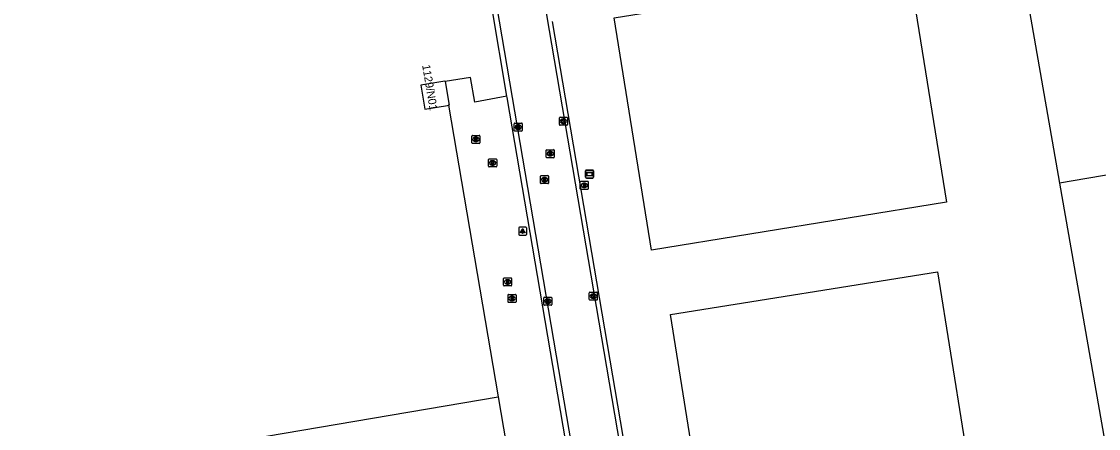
# Model space of a CAD drawing. Extents: x 154324 to 155743, y 382939 to 384183.
# Drawn here: x 154819.6 to 154954.2, y 383617.3 to 383668.1 of the extents above; entities that cross this region are included whole.
import ezdxf

# ---------------------------------------------------------------- set-up
doc = ezdxf.new("R2010")
doc.units = 0
for name, color, linetype in [('IMGEO_Brandkraan', 7, 'Continuous'), ('IMGEO_Erf', 7, 'Continuous'), ('IMGEO_Grasland_agrarisch', 7, 'Continuous'), ('IMGEO_Kolk', 7, 'Continuous'), ('IMGEO_Lichtpunt', 7, 'Continuous'), ('IMGEO_Muur', 7, 'Continuous'), ('IMGEO_Pand', 7, 'Continuous'), ('IMGEO_Pand_nummerreeks', 7, 'Continuous'), ('IMGEO_Pand_vergunning_verleend', 7, 'Continuous'), ('IMGEO_Rijbaan_lokaal_gesloten', 7, 'Continuous'), ('IMGEO_Rijbaan_lokaal_open', 7, 'Continuous'), ('IMGEO_Rioolput', 7, 'Continuous'), ('IMGEO_Verklikker', 7, 'Continuous')]:
    doc.layers.add(name, color=color, linetype=linetype)

msp = doc.modelspace()

# ---------------------------------------------------------------- linework, layer by layer
at = {"layer": 'IMGEO_Brandkraan'}
for p, q in [((154889.46, 383647.21), (154889.46, 383648.06)), ((154889.54, 383648.13), (154890.39, 383648.13)), ((154889.95, 383647.91), (154889.97, 383647.91)), ((154890.46, 383648.06), (154890.46, 383647.21)), ((154890.39, 383647.13), (154889.54, 383647.13)), ((154889.97, 383647.35), (154889.95, 383647.35))]:
    msp.add_line(p, q, dxfattribs=at)
for points in [[(154889.46, 383647.21), (154889.46, 383648.06)], [(154889.54, 383648.13), (154890.39, 383648.13)], [(154889.81, 383647.83), (154889.81, 383647.43), (154890.02, 383647.43)], [(154890.04, 383647.83), (154889.81, 383647.83)], [(154889.99, 383647.75), (154889.93, 383647.75), (154889.93, 383647.68)], [(154889.93, 383647.68), (154889.99, 383647.68)], [(154890, 383647.6), (154889.93, 383647.6), (154889.93, 383647.52)], [(154889.93, 383647.52), (154890, 383647.52)], [(154890.46, 383648.06), (154890.46, 383647.21)], [(154890.39, 383647.13), (154889.54, 383647.13)]]:
    msp.add_lwpolyline(points, dxfattribs=at)
for centre, radius, start, end in [((154889.54, 383648.06), 0.0765, 91.552, 178.448), ((154889.54, 383648.06), 0.0765, 91.552, 178.448), ((154889.99, 383647.71), 0.0379, 267.8285, 90.9355), ((154890, 383647.56), 0.0404, 269.8759, 90.5077), ((154890.03, 383647.68), 0.251, 268.6676, 293.5347), ((154890.04, 383647.69), 0.145, 59.4692, 91.5367), ((154890.07, 383647.74), 0.0922, 285.5137, 58.1501), ((154890.07, 383647.54), 0.105, 301.3115, 78.989), ((154890.39, 383648.06), 0.0765, 1.552, 88.448), ((154890.39, 383648.06), 0.0765, 1.552, 88.448), ((154889.54, 383647.21), 0.0765, 181.552, 268.448), ((154889.54, 383647.21), 0.0765, 181.552, 268.448), ((154890.39, 383647.21), 0.0765, 271.552, 358.448), ((154890.39, 383647.21), 0.0765, 271.552, 358.448)]:
    msp.add_arc(centre, radius, start, end, dxfattribs=at)
for centre, major_axis, ratio, start_param, end_param in [((154889.95, 383647.63), (-0.387, 0.002), 0.722429, 4.712389, 7.853982), ((154889.97, 383647.63), (-0.39, 0.002), 0.717154, 1.570796, 4.712389)]:
    msp.add_ellipse(centre, major_axis=major_axis, ratio=ratio, start_param=start_param, end_param=end_param, dxfattribs=at)
at = {"layer": 'IMGEO_Erf'}
for points in [[(154880.3, 383658.76), (154876.27, 383658.02), (154875.75, 383661.08), (154872.56, 383660.61)], [(154872.98, 383657.63), (154879.18, 383621.22)]]:
    msp.add_lwpolyline(points, dxfattribs=at)
at = {"layer": 'IMGEO_Grasland_agrarisch'}
msp.add_lwpolyline([(154895.23, 383669.68), (154944.1, 383677.97), (154949.34, 383647.91), (154982.71, 383457.88)], dxfattribs=at)
at = {"layer": 'IMGEO_Kolk'}
for p, q in [((154886.85, 383655.21), (154886.85, 383656.06)), ((154886.93, 383656.14), (154887.78, 383656.14)), ((154887.34, 383655.92), (154887.36, 383655.92)), ((154887.85, 383656.06), (154887.85, 383655.21)), ((154881.2, 383654.47), (154881.2, 383655.33)), ((154881.28, 383655.4), (154882.13, 383655.4)), ((154882.13, 383654.4), (154881.28, 383654.4)), ((154881.69, 383655.18), (154881.72, 383655.18)), ((154881.71, 383654.62), (154881.69, 383654.62)), ((154882.2, 383655.33), (154882.2, 383654.47)), ((154887.78, 383655.14), (154886.93, 383655.14)), ((154887.36, 383655.36), (154887.34, 383655.36)), ((154890.59, 383633.37), (154890.59, 383634.22)), ((154890.67, 383634.29), (154891.52, 383634.29)), ((154891.08, 383634.07), (154891.11, 383634.07)), ((154891.59, 383634.22), (154891.59, 383633.37)), ((154884.91, 383632.73), (154884.91, 383633.59)), ((154884.98, 383633.66), (154885.83, 383633.66)), ((154885.83, 383632.66), (154884.98, 383632.66)), ((154885.39, 383633.44), (154885.42, 383633.44)), ((154885.42, 383632.88), (154885.39, 383632.88)), ((154885.91, 383633.59), (154885.91, 383632.73)), ((154891.52, 383633.29), (154890.67, 383633.29)), ((154891.1, 383633.51), (154891.08, 383633.51))]:
    msp.add_line(p, q, dxfattribs=at)
for points in [[(154886.85, 383655.21), (154886.85, 383656.06)], [(154886.93, 383656.14), (154887.78, 383656.14)], [(154887.17, 383655.84), (154887.3, 383655.84), (154887.3, 383655.69), (154887.42, 383655.84), (154887.59, 383655.84), (154887.44, 383655.69), (154887.6, 383655.44), (154887.44, 383655.44), (154887.36, 383655.6), (154887.3, 383655.53), (154887.3, 383655.44), (154887.17, 383655.44), (154887.17, 383655.84)], [(154887.85, 383656.06), (154887.85, 383655.21)], [(154881.2, 383654.47), (154881.2, 383655.33)], [(154881.28, 383655.4), (154882.13, 383655.4)], [(154882.13, 383654.4), (154881.28, 383654.4)], [(154881.52, 383655.1), (154881.65, 383655.1), (154881.65, 383654.95), (154881.78, 383655.1), (154881.94, 383655.1), (154881.79, 383654.95), (154881.95, 383654.7), (154881.79, 383654.7), (154881.71, 383654.86), (154881.65, 383654.8), (154881.65, 383654.7), (154881.52, 383654.7), (154881.52, 383655.1)], [(154882.2, 383655.33), (154882.2, 383654.47)], [(154887.78, 383655.14), (154886.93, 383655.14)], [(154890.59, 383633.37), (154890.59, 383634.22)], [(154890.67, 383634.29), (154891.52, 383634.29)], [(154890.91, 383633.99), (154891.04, 383633.99), (154891.04, 383633.84), (154891.17, 383633.99), (154891.33, 383633.99), (154891.19, 383633.84), (154891.34, 383633.59), (154891.19, 383633.59), (154891.1, 383633.76), (154891.04, 383633.69), (154891.04, 383633.59), (154890.91, 383633.59), (154890.91, 383633.99)], [(154891.59, 383634.22), (154891.59, 383633.37)], [(154884.91, 383632.73), (154884.91, 383633.59)], [(154884.98, 383633.66), (154885.83, 383633.66)], [(154885.83, 383632.66), (154884.98, 383632.66)], [(154885.23, 383633.36), (154885.35, 383633.36), (154885.35, 383633.21), (154885.48, 383633.36), (154885.64, 383633.36), (154885.5, 383633.21), (154885.65, 383632.96), (154885.5, 383632.96), (154885.41, 383633.13), (154885.35, 383633.06), (154885.35, 383632.96), (154885.23, 383632.96), (154885.23, 383633.36)], [(154885.91, 383633.59), (154885.91, 383632.73)], [(154891.52, 383633.29), (154890.67, 383633.29)]]:
    msp.add_lwpolyline(points, dxfattribs=at)
for centre, start, end in [((154886.93, 383656.06), 91.552, 178.448), ((154886.93, 383656.06), 91.552, 178.448), ((154887.78, 383656.06), 1.552, 88.448), ((154887.78, 383656.06), 1.552, 88.448), ((154881.28, 383655.32), 91.552, 178.448), ((154881.28, 383655.32), 91.552, 178.448), ((154881.28, 383654.47), 181.552, 268.448), ((154881.28, 383654.47), 181.552, 268.448), ((154882.13, 383655.32), 1.552, 88.448), ((154882.13, 383655.32), 1.552, 88.448), ((154882.13, 383654.47), 271.552, 358.448), ((154882.13, 383654.47), 271.552, 358.448), ((154886.93, 383655.21), 181.552, 268.448), ((154886.93, 383655.21), 181.552, 268.448), ((154887.78, 383655.21), 271.552, 358.448), ((154887.78, 383655.21), 271.552, 358.448), ((154890.67, 383634.22), 91.552, 178.448), ((154890.67, 383634.22), 91.552, 178.448), ((154891.52, 383634.22), 1.552, 88.448), ((154891.52, 383634.22), 1.552, 88.448), ((154884.98, 383633.59), 91.552, 178.448), ((154884.98, 383633.59), 91.552, 178.448), ((154884.98, 383632.74), 181.552, 268.448), ((154884.98, 383632.74), 181.552, 268.448), ((154885.83, 383633.59), 1.552, 88.448), ((154885.83, 383633.59), 1.552, 88.448), ((154885.83, 383632.74), 271.552, 358.448), ((154885.83, 383632.74), 271.552, 358.448), ((154890.67, 383633.37), 181.552, 268.448), ((154890.67, 383633.37), 181.552, 268.448), ((154891.52, 383633.37), 271.552, 358.448), ((154891.52, 383633.37), 271.552, 358.448)]:
    msp.add_arc(centre, 0.0765, start, end, dxfattribs=at)
for centre, major_axis, ratio, start_param, end_param in [((154887.34, 383655.64), (-0.387, 0.002), 0.722429, 4.712389, 7.853982), ((154887.36, 383655.64), (-0.39, 0.002), 0.717154, 1.570796, 4.712389), ((154881.69, 383654.9), (-0.387, 0.002), 0.722429, 4.712389, 7.853982), ((154881.71, 383654.9), (-0.39, 0.002), 0.717154, 1.570796, 4.712389), ((154891.08, 383633.79), (-0.387, 0.002), 0.722429, 4.712389, 7.853982), ((154891.1, 383633.79), (-0.39, 0.002), 0.717154, 1.570796, 4.712389), ((154885.39, 383633.16), (-0.387, 0.002), 0.722429, 4.712389, 7.853982), ((154885.42, 383633.16), (-0.39, 0.002), 0.717154, 1.570796, 4.712389)]:
    msp.add_ellipse(centre, major_axis=major_axis, ratio=ratio, start_param=start_param, end_param=end_param, dxfattribs=at)
at = {"layer": 'IMGEO_Lichtpunt'}
for p, q in [((154881.76, 383642.31), (154881.76, 383641.51)), ((154881.76, 383642.31), (154881.76, 383641.51)), ((154882.66, 383642.41), (154881.86, 383642.41)), ((154882.66, 383642.41), (154881.86, 383642.41)), ((154882.76, 383641.51), (154882.76, 383642.31)), ((154882.76, 383641.51), (154882.76, 383642.31)), ((154881.86, 383641.41), (154882.66, 383641.41)), ((154881.86, 383641.41), (154882.66, 383641.41))]:
    msp.add_line(p, q, dxfattribs=at)
for points in [[(154882.14, 383641.98), (154882.17, 383641.95), (154881.99, 383641.69), (154881.95, 383641.72), (154882.14, 383641.98)], [(154882.24, 383641.93), (154882.29, 383641.93), (154882.29, 383641.61), (154882.24, 383641.61), (154882.24, 383641.93)], [(154882.35, 383641.95), (154882.39, 383641.98), (154882.57, 383641.71), (154882.53, 383641.69), (154882.35, 383641.95)]]:
    msp.add_lwpolyline(points, dxfattribs=at)
msp.add_circle((154882.26, 383642.11), 0.0994, dxfattribs=at)
for centre, start, end in [((154881.86, 383642.31), 90, 180), ((154881.86, 383642.31), 90, 180), ((154882.66, 383642.31), 0, 90), ((154882.66, 383642.31), 0, 90), ((154881.86, 383641.51), 180, 270), ((154881.86, 383641.51), 180, 270), ((154882.66, 383641.51), 270, 0), ((154882.66, 383641.51), 270, 360)]:
    msp.add_arc(centre, 0.0946, start, end, dxfattribs=at)
at = {"layer": 'IMGEO_Muur'}
msp.add_lwpolyline([(154989.9, 383654.82), (154949.34, 383647.91)], dxfattribs=at)
at = {"layer": 'IMGEO_Pand'}
for points in [[(154872.56, 383660.61), (154872.55, 383660.64), (154869.54, 383660.13), (154870.05, 383657.16), (154872.88, 383657.62), (154872.98, 383657.63)], [(154872.56, 383660.61), (154873.07, 383657.65), (154872.98, 383657.63)], [(154717.25, 383593.65), (154799.26, 383607.57), (154796.3, 383624.97), (154807.03, 383626.73), (154809.97, 383609.47), (154879.18, 383621.22)], [(154879.18, 383621.22), (154895.56, 383525.11), (154815.63, 383511.49), (154769.14, 383503.59), (154738.94, 383498.45)]]:
    msp.add_lwpolyline(points, dxfattribs=at)
at = {"layer": 'IMGEO_Pand_vergunning_verleend'}
for points in [[(154893.69, 383668.53), (154930.56, 383674.49), (154935.25, 383645.51), (154898.38, 383639.55), (154893.69, 383668.53)], [(154900.72, 383631.49), (154934.09, 383636.84), (154938.99, 383606.36), (154905.61, 383601.01), (154900.72, 383631.49)]]:
    msp.add_lwpolyline(points, dxfattribs=at)
at = {"layer": 'IMGEO_Rijbaan_lokaal_gesloten'}
for points in [[(154859.21, 383821.78), (154860.59, 383813.67), (154872.99, 383740.87), (154875.26, 383727.61), (154875.73, 383724.69), (154937.89, 383359.92)], [(154854.43, 383814.31), (154854.65, 383812.99), (154854.81, 383812.02), (154858.48, 383790.5), (154869.56, 383725.26), (154869.6, 383725.13), (154932.04, 383358.96)]]:
    msp.add_lwpolyline(points, dxfattribs=at)
at = {"layer": 'IMGEO_Rijbaan_lokaal_open'}
for points in [[(154880.3, 383658.76), (154878.39, 383669.9)], [(154936.7, 383370.54), (154936.69, 383370.6), (154886, 383668.1)], [(154931.45, 383358.87), (154880.33, 383658.59), (154880.3, 383658.76)]]:
    msp.add_lwpolyline(points, dxfattribs=at)
at = {"layer": 'IMGEO_Rioolput'}
for p, q in [((154875.91, 383652.94), (154875.91, 383653.79)), ((154875.99, 383653.87), (154876.84, 383653.87)), ((154876.84, 383652.87), (154875.99, 383652.87)), ((154876.4, 383653.65), (154876.43, 383653.65)), ((154876.42, 383653.09), (154876.4, 383653.09)), ((154876.92, 383653.79), (154876.92, 383652.94)), ((154885.21, 383651.16), (154885.21, 383652.01)), ((154885.28, 383652.08), (154886.13, 383652.08)), ((154885.69, 383651.86), (154885.72, 383651.86)), ((154886.21, 383652.01), (154886.21, 383651.16)), ((154878, 383650.01), (154878, 383650.86)), ((154878.08, 383650.93), (154878.93, 383650.93)), ((154878.49, 383650.71), (154878.52, 383650.71)), ((154878.51, 383650.15), (154878.49, 383650.15)), ((154879.01, 383650.86), (154879.01, 383650.01)), ((154886.13, 383651.08), (154885.28, 383651.08)), ((154885.72, 383651.3), (154885.69, 383651.3)), ((154878.93, 383649.93), (154878.08, 383649.93)), ((154884.5, 383647.92), (154884.5, 383648.77)), ((154884.57, 383648.84), (154885.42, 383648.84)), ((154885.5, 383648.77), (154885.5, 383647.92)), ((154885.42, 383647.84), (154884.57, 383647.84)), ((154884.98, 383648.62), (154885.01, 383648.62)), ((154885.01, 383648.06), (154884.98, 383648.06)), ((154879.88, 383635.15), (154879.88, 383636)), ((154879.95, 383636.07), (154880.81, 383636.07)), ((154880.39, 383635.29), (154880.36, 383635.29)), ((154880.37, 383635.85), (154880.39, 383635.85)), ((154880.88, 383636), (154880.88, 383635.15)), ((154880.81, 383635.07), (154879.95, 383635.07)), ((154880.5, 383634.01), (154881.35, 383634.01)), ((154880.43, 383633.08), (154880.43, 383633.93)), ((154881.35, 383633), (154880.5, 383633)), ((154880.91, 383633.78), (154880.94, 383633.78)), ((154880.94, 383633.23), (154880.91, 383633.23)), ((154881.43, 383633.93), (154881.43, 383633.08))]:
    msp.add_line(p, q, dxfattribs=at)
for points in [[(154875.91, 383652.94), (154875.91, 383653.79)], [(154875.99, 383653.87), (154876.84, 383653.87)], [(154876.84, 383652.87), (154875.99, 383652.87)], [(154876.5, 383653.56), (154876.25, 383653.57), (154876.25, 383653.17)], [(154876.25, 383653.17), (154876.38, 383653.17), (154876.38, 383653.33), (154876.39, 383653.33)], [(154876.43, 383653.49), (154876.38, 383653.49), (154876.38, 383653.4)], [(154876.38, 383653.4), (154876.43, 383653.4)], [(154876.43, 383653.3), (154876.5, 383653.17), (154876.64, 383653.17), (154876.58, 383653.29)], [(154876.92, 383653.79), (154876.92, 383652.94)], [(154885.21, 383651.16), (154885.21, 383652.01)], [(154885.28, 383652.08), (154886.13, 383652.08)], [(154885.8, 383651.78), (154885.54, 383651.78), (154885.54, 383651.38)], [(154885.54, 383651.38), (154885.67, 383651.38), (154885.67, 383651.55), (154885.68, 383651.55)], [(154885.72, 383651.7), (154885.67, 383651.7), (154885.67, 383651.62)], [(154885.67, 383651.62), (154885.72, 383651.62)], [(154885.72, 383651.52), (154885.8, 383651.38), (154885.94, 383651.38), (154885.87, 383651.51)], [(154886.21, 383652.01), (154886.21, 383651.16)], [(154878, 383650.01), (154878, 383650.86)], [(154878.08, 383650.93), (154878.93, 383650.93)], [(154878.59, 383650.63), (154878.34, 383650.63), (154878.34, 383650.23)], [(154878.34, 383650.23), (154878.47, 383650.23), (154878.47, 383650.4), (154878.48, 383650.4)], [(154878.52, 383650.55), (154878.47, 383650.55), (154878.47, 383650.47)], [(154878.47, 383650.47), (154878.52, 383650.47)], [(154878.52, 383650.37), (154878.59, 383650.23), (154878.73, 383650.23), (154878.67, 383650.36)], [(154879.01, 383650.86), (154879.01, 383650.01)], [(154886.13, 383651.08), (154885.28, 383651.08)], [(154878.93, 383649.93), (154878.08, 383649.93)], [(154884.5, 383647.92), (154884.5, 383648.77)], [(154884.57, 383648.84), (154885.42, 383648.84)], [(154885.5, 383648.77), (154885.5, 383647.92)], [(154885.42, 383647.84), (154884.57, 383647.84)], [(154885.08, 383648.54), (154884.83, 383648.54), (154884.83, 383648.14)], [(154884.83, 383648.14), (154884.96, 383648.14), (154884.96, 383648.31), (154884.97, 383648.31)], [(154885.01, 383648.46), (154884.96, 383648.46), (154884.96, 383648.38)], [(154884.96, 383648.38), (154885.01, 383648.38)], [(154885.01, 383648.28), (154885.09, 383648.14), (154885.22, 383648.14), (154885.16, 383648.27)], [(154879.88, 383635.15), (154879.88, 383636)], [(154879.95, 383636.07), (154880.81, 383636.07)], [(154880.47, 383635.77), (154880.22, 383635.77), (154880.22, 383635.37)], [(154880.22, 383635.37), (154880.34, 383635.37), (154880.34, 383635.54), (154880.35, 383635.54)], [(154880.39, 383635.69), (154880.34, 383635.69), (154880.34, 383635.61)], [(154880.34, 383635.61), (154880.39, 383635.61)], [(154880.4, 383635.51), (154880.47, 383635.37), (154880.61, 383635.37), (154880.54, 383635.5)], [(154880.88, 383636), (154880.88, 383635.15)], [(154880.81, 383635.07), (154879.95, 383635.07)], [(154880.5, 383634.01), (154881.35, 383634.01)], [(154880.43, 383633.08), (154880.43, 383633.93)], [(154881.35, 383633), (154880.5, 383633)], [(154881.02, 383633.7), (154880.76, 383633.7), (154880.76, 383633.3)], [(154880.76, 383633.3), (154880.89, 383633.3), (154880.89, 383633.47), (154880.9, 383633.47)], [(154880.94, 383633.62), (154880.89, 383633.62), (154880.89, 383633.54)], [(154880.89, 383633.54), (154880.94, 383633.54)], [(154880.94, 383633.44), (154881.02, 383633.3), (154881.16, 383633.3), (154881.09, 383633.43)], [(154881.43, 383633.93), (154881.43, 383633.08)]]:
    msp.add_lwpolyline(points, dxfattribs=at)
for centre, radius, start, end in [((154875.99, 383653.79), 0.0765, 91.552, 178.448), ((154875.99, 383653.79), 0.0765, 91.552, 178.448), ((154875.99, 383652.94), 0.0765, 181.552, 268.448), ((154875.99, 383652.94), 0.0765, 181.552, 268.448), ((154876.38, 383653.28), 0.0533, 26.0293, 88.6989), ((154876.43, 383653.39), 0.0964, 77.0061, 93.1865), ((154876.41, 383653.59), 0.19, 274.7715, 282.9687), ((154876.45, 383653.45), 0.0378, 276.6634, 79.6772), ((154876.5, 383653.46), 0.109, 350.3612, 89.416), ((154876.5, 383653.45), 0.112, 277.5842, 350.9817), ((154876.48, 383653.24), 0.108, 29.5134, 73.7905), ((154876.84, 383653.79), 0.0765, 1.552, 88.448), ((154876.84, 383653.79), 0.0765, 1.552, 88.448), ((154876.84, 383652.94), 0.0765, 271.552, 358.448), ((154876.84, 383652.94), 0.0765, 271.552, 358.448), ((154885.28, 383652.01), 0.0765, 91.552, 178.448), ((154885.28, 383652.01), 0.0765, 91.552, 178.448), ((154885.68, 383651.49), 0.0533, 26.0293, 88.6989), ((154885.73, 383651.61), 0.0964, 77.0061, 93.1865), ((154885.7, 383651.81), 0.19, 274.7715, 282.9687), ((154885.74, 383651.66), 0.0378, 276.6634, 79.6772), ((154885.79, 383651.67), 0.109, 350.3612, 89.416), ((154885.79, 383651.67), 0.112, 277.5842, 350.9817), ((154885.78, 383651.46), 0.108, 29.5134, 73.7905), ((154886.13, 383652.01), 0.0765, 1.552, 88.448), ((154886.13, 383652.01), 0.0765, 1.552, 88.448), ((154878.08, 383650.86), 0.0765, 91.552, 178.448), ((154878.08, 383650.86), 0.0765, 91.552, 178.448), ((154878.47, 383650.34), 0.0533, 26.0293, 88.6989), ((154878.52, 383650.46), 0.0964, 77.0061, 93.1865), ((154878.5, 383650.66), 0.19, 274.7715, 282.9687), ((154878.54, 383650.51), 0.0378, 276.6634, 79.6772), ((154878.59, 383650.52), 0.109, 350.3612, 89.416), ((154878.59, 383650.52), 0.112, 277.5842, 350.9817), ((154878.57, 383650.31), 0.108, 29.5134, 73.7905), ((154878.93, 383650.86), 0.0765, 1.552, 88.448), ((154878.93, 383650.86), 0.0765, 1.552, 88.448), ((154885.28, 383651.16), 0.0765, 181.552, 268.448), ((154885.28, 383651.16), 0.0765, 181.552, 268.448), ((154886.13, 383651.16), 0.0765, 271.552, 358.448), ((154886.13, 383651.16), 0.0765, 271.552, 358.448), ((154878.08, 383650.01), 0.0765, 181.552, 268.448), ((154878.08, 383650.01), 0.0765, 181.552, 268.448), ((154878.93, 383650.01), 0.0765, 271.552, 358.448), ((154878.93, 383650.01), 0.0765, 271.552, 358.448), ((154884.57, 383648.77), 0.0765, 91.552, 178.448), ((154884.57, 383648.77), 0.0765, 91.552, 178.448), ((154885.42, 383648.77), 0.0765, 1.552, 88.448), ((154885.42, 383648.77), 0.0765, 1.552, 88.448), ((154884.57, 383647.92), 0.0765, 181.552, 268.448), ((154884.57, 383647.92), 0.0765, 181.552, 268.448), ((154884.97, 383648.25), 0.0533, 26.0293, 88.6989), ((154885.02, 383648.37), 0.0964, 77.0061, 93.1865), ((154884.99, 383648.57), 0.19, 274.7715, 282.9687), ((154885.03, 383648.42), 0.0378, 276.6634, 79.6772), ((154885.08, 383648.43), 0.109, 350.3612, 89.416), ((154885.08, 383648.43), 0.112, 277.5842, 350.9817), ((154885.07, 383648.22), 0.108, 29.5134, 73.7905), ((154885.42, 383647.92), 0.0765, 271.552, 358.448), ((154885.42, 383647.92), 0.0765, 271.552, 358.448), ((154879.96, 383636), 0.0765, 91.552, 178.448), ((154879.96, 383636), 0.0765, 91.552, 178.448), ((154880.35, 383635.48), 0.0533, 26.0293, 88.6989), ((154880.4, 383635.6), 0.0964, 77.0061, 93.1865), ((154880.38, 383635.8), 0.19, 274.7715, 282.9687), ((154880.41, 383635.65), 0.0378, 276.6634, 79.6772), ((154880.47, 383635.66), 0.109, 350.3612, 89.416), ((154880.47, 383635.66), 0.112, 277.5842, 350.9817), ((154880.45, 383635.45), 0.108, 29.5134, 73.7905), ((154880.8, 383636), 0.0765, 1.552, 88.448), ((154880.8, 383636), 0.0765, 1.552, 88.448), ((154879.96, 383635.15), 0.0765, 181.552, 268.448), ((154879.96, 383635.15), 0.0765, 181.552, 268.448), ((154880.5, 383633.93), 0.0765, 91.552, 178.448), ((154880.5, 383633.93), 0.0765, 91.552, 178.448), ((154880.8, 383635.15), 0.0765, 271.552, 358.448), ((154880.8, 383635.15), 0.0765, 271.552, 358.448), ((154881.35, 383633.93), 0.0765, 1.552, 88.448), ((154881.35, 383633.93), 0.0765, 1.552, 88.448), ((154880.5, 383633.08), 0.0765, 181.552, 268.448), ((154880.5, 383633.08), 0.0765, 181.552, 268.448), ((154880.9, 383633.41), 0.0533, 26.0293, 88.6989), ((154880.95, 383633.53), 0.0964, 77.0061, 93.1865), ((154880.92, 383633.73), 0.19, 274.7715, 282.9687), ((154880.96, 383633.58), 0.0378, 276.6634, 79.6772), ((154881.01, 383633.59), 0.109, 350.3612, 89.416), ((154881.01, 383633.59), 0.112, 277.5842, 350.9817), ((154881, 383633.38), 0.108, 29.5134, 73.7905), ((154881.35, 383633.08), 0.0765, 271.552, 358.448), ((154881.35, 383633.08), 0.0765, 271.552, 358.448)]:
    msp.add_arc(centre, radius, start, end, dxfattribs=at)
for centre, major_axis, ratio, start_param, end_param in [((154876.4, 383653.37), (-0.387, 0.002), 0.722429, 4.712389, 7.853982), ((154876.43, 383653.37), (-0.39, 0.002), 0.717154, 1.570796, 4.712389), ((154885.69, 383651.58), (-0.387, 0.002), 0.722429, 4.712389, 7.853982), ((154885.72, 383651.58), (-0.39, 0.002), 0.717154, 1.570796, 4.712389), ((154878.49, 383650.43), (-0.387, 0.002), 0.722429, 4.712389, 7.853982), ((154878.52, 383650.43), (-0.39, 0.002), 0.717154, 1.570796, 4.712389), ((154884.98, 383648.34), (-0.387, 0.002), 0.722429, 4.712389, 7.853982), ((154885.01, 383648.34), (-0.39, 0.002), 0.717154, 1.570796, 4.712389), ((154880.37, 383635.57), (-0.387, 0.002), 0.722429, 4.712389, 7.853982), ((154880.39, 383635.57), (-0.39, 0.002), 0.717154, 1.570796, 4.712389), ((154880.91, 383633.5), (-0.387, 0.002), 0.722429, 4.712389, 7.853982), ((154880.94, 383633.5), (-0.39, 0.002), 0.717154, 1.570796, 4.712389)]:
    msp.add_ellipse(centre, major_axis=major_axis, ratio=ratio, start_param=start_param, end_param=end_param, dxfattribs=at)
at = {"layer": 'IMGEO_Verklikker'}
for p, q in [((154890.13, 383648.64), (154890.13, 383649.44)), ((154890.13, 383649.44), (154890.13, 383648.64)), ((154890.23, 383649.54), (154891.02, 383649.54)), ((154891.02, 383649.54), (154890.23, 383649.54)), ((154891.12, 383649.44), (154891.12, 383648.64)), ((154891.12, 383648.64), (154891.12, 383649.44)), ((154891.02, 383648.54), (154890.23, 383648.54)), ((154890.23, 383648.54), (154891.02, 383648.54))]:
    msp.add_line(p, q, dxfattribs=at)
for points in [[(154890.23, 383649.27), (154891.02, 383649.27), (154891.02, 383648.81), (154890.23, 383648.81), (154890.23, 383649.27)], [(154890.3, 383649.21), (154890.3, 383648.87), (154890.96, 383648.87), (154890.96, 383649.21), (154890.3, 383649.21)]]:
    msp.add_lwpolyline(points, dxfattribs=at)
for centre, start, end in [((154890.23, 383649.44), 90, 180), ((154890.23, 383649.44), 90, 180), ((154891.02, 383649.44), 0, 90), ((154891.02, 383649.44), 360, 90), ((154890.23, 383648.64), 180, 270), ((154890.23, 383648.64), 180, 270), ((154891.02, 383648.64), 270, 0), ((154891.02, 383648.64), 270, 0)]:
    msp.add_arc(centre, 0.1, start, end, dxfattribs=at)

# ---------------------------------------------------------------- texts
at = {"layer": 'IMGEO_Pand_nummerreeks'}
msp.add_text('1129/N01', height=1, rotation=279.5682, dxfattribs=at).set_placement((154869.69, 383662.63))

doc.saveas('drawing.dxf')
